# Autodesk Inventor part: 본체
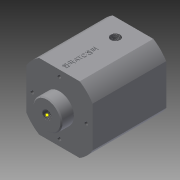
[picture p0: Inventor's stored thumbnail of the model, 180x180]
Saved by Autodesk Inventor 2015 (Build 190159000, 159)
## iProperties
Created: 2020-02
Part Number: 본체
Material: 일반
Document SubType Name: Modeling
Designer: 1026954
Density: 1 g/cm^3
Appearance: 기본값
Author: 1026954
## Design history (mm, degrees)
sketch "스케치1"
  geometry: L1 (-32, -32)-(32, -32); L2 (32, -32)-(32, 32); L3 (32, 32)-(-32, 32); L4 (-32, 32)-(-32, -32); L5 (-32, -32)-(32, 32); L6 (32, -32)-(-32, 32); C1 r 37.5 at (0, 0); 1 further point
  constraints: 12 end point, 2 midpoint, 2 parallel, 1 centre point, 1 coincident, 1 horizontal, 1 perpendicular
  dimensions: "d0" = 75 diameter of C1; "d1" = 64 distance of L3.end L2.end; "d2" = 64 distance of L2.end L1.end
extrude "돌출1" new body sketch "스케치1" distance "d3" = 83; taper "d4" = 0 deg
sketch "스케치2" dims "d5" = 75
  geometry: L1 (-32, 32)-(-19.551, 32); L2 (-32, 32)-(32, 32) reference; L3 (-32, 32)-(-32, 19.551); L4 (-32, -32)-(-32, 32) reference; L5 (32, 32)-(19.551, 32); L6 (32, 32)-(32, 19.551); L7 (32, 32)-(32, -32) reference; L8 (32, -32)-(32, -19.551); L9 (32, -32)-(19.551, -32); L10 (32, -32)-(-32, -32) reference; L11 (-32, -32)-(-32, -19.551); L12 (-32, -32)-(-19.551, -32); 2 further points
  constraints: 16 end point, 8 point on line, 1 coincident, 10 other
extrude "돌출2" cut sketch "스케치2" stored distance "d6" = 82; taper "d7" = 0 deg
sketch "스케치3"
  geometry: L1 (32, -32)-(-32, -32); L2 (-32, -32)-(-32, 32); L3 (-32, 32)-(32, 32); L4 (32, 32)-(32, -32); L5 (32, -32)-(-32, 32); L6 (-32, -32)-(32, 32); C1 r 14 at (0, 0); C2 r 37.5 at (0, 0); 1 further point
  constraints: 12 end point, 2 centre point, 2 coincident, 2 midpoint, 2 parallel, 1 horizontal, 1 perpendicular
  dimensions: "d8" = 28 diameter of C1; "d9" = 75 diameter of C2; "d10" = 64 distance of L2.end L3.end; "d11" = 64 distance of L1.end L2.end
extrude "돌출3" cut sketch "스케치3" distance "d12" = 12; taper "d13" = 0 deg
sketch "스케치4"
  geometry: C1 r 14 at (0, 0) reference; 1 further point
hole "구멍1" sketch "스케치4" at (0, 0) diameter "d14" = 8.917; stored, may be unused: countersink angle "d18" = 90 deg, drill point angle "d20" = 118 deg; dims "d15" = 14, "d16" = 4, "d17" = 2, "d19" = 17
sketch "스케치5"
  geometry: C1 r 4.458 at (0, 0) reference; C2 r 14 at (0, 0) reference; C3 r 2 at (0, 0); 1 further point
  constraints: 1 centre point, 1 coincident
  dimensions: "d21" = 4 diameter of C3
extrude "돌출4" cut sketch "스케치5" stored distance "d22" = 12; taper "d23" = 0 deg
sketch "스케치6"
  geometry: L1 (0, 0)-(0, 26)
  constraints: 2 end point, 1 vertical
  dimensions: "d24" = 26 distance of L1.start L1.end
hole "구멍2" sketch "스케치6" at (0, 26) diameter "d25" = 3.459; stored, may be unused: countersink angle "d29" = 90 deg, drill point angle "d31" = 118 deg; dims "d26" = 10, "d27" = 4, "d28" = 2, "d30" = 12
sketch "스케치7"
  geometry: L1 (39.102, -71)-(0, -71) reference; L2 (0, -71)-(0, 0) reference; L3 (0, 0)-(39.102, 0) reference; L4 (39.102, 0)-(39.102, -71) reference; L5 (19.551, 0)-(19.551, -17); 1 further point
  constraints: 2 end point, 1 midpoint, 1 vertical
  dimensions: "d35" = 17 distance of L5.start L5.end
hole "구멍3" sketch "스케치7" at (19.551, -17) diameter "d36" = 8.917; stored, may be unused: countersink angle "d40" = 90 deg, drill point angle "d42" = 118 deg; dims "d37" = 6, "d38" = 4, "d39" = 2, "d41" = 9
sketch "스케치8"
  geometry: L1 (39.102, -71)-(0, -71) reference; L2 (0, -71)-(0, 0) reference; L3 (0, 0)-(39.102, 0) reference; L4 (39.102, 0)-(39.102, -71) reference; C1 r 4.458 at (19.551, -17) reference; C2 r 2 at (19.551, -17); 1 further point
  constraints: 1 centre point, 1 coincident
  dimensions: "d43" = 4 diameter of C2
extrude "돌출5" cut sketch "스케치8" distance "d44" = 40; taper "d45" = 0 deg
sketch "스케치9"
  geometry: C1 r 20 at (0, 0); 1 further point
  constraints: 1 centre point, 1 coincident
  dimensions: "d46" = 40 diameter of C1
extrude "돌출6" cut sketch "스케치9" distance "d47" = 62; taper "d48" = 0 deg
sketch "스케치10"
  geometry: L1 (0, 0)-(0, -21.224); L2 (0, 0)-(22.517, -13); L3 (0, 0)-(-22.517, -13); L4 (0, 0)-(0, 26); C1 r 1.73 at (0, 26) reference; A1 r 26 centre (0, 0) between (22.517, -13) and (-22.517, -13)
  constraints: 8 end point, 2 point on circle, 2 vertical, 1 centre point, 1 coincident
  dimensions: "d49" = 52 diameter of A1; "d50" = 60 deg angle of L1 L2; "d51" = 60 deg angle of L1 L3
hole "구멍4" sketch "스케치10" at (22.517, -13), (-22.517, -13), (0, 26) diameter "d52" = 3.459; stored, may be unused: countersink angle "d56" = 90 deg, drill point angle "d58" = 118 deg; dims "d53" = 10, "d54" = 4, "d55" = 2, "d57" = 12
sketch "스케치11"
  geometry: L1 (5.551, -71)-(33.551, -71) reference; L2 (5.551, -83)-(33.551, -83) reference; L3 (0, -71)-(39.102, -71) reference; L4 (39.102, -71)-(39.102, 0) reference; L5 (0, 0)-(39.102, 0) reference; L6 (0, 0)-(0, -71) reference; C1 r 4.458 at (19.551, -17) reference; 3 further points
  constraints: 1 midpoint, 1 vertical alignment, 1 other
  dimensions: "d59" = 20 distance from line of L1 point (19.551, -51)
feature "엠보싱1" sketch "스케치11" dims "d0" = 75, "d1" = 64, "d2" = 64, "d60" = 0.5, "d61" = 0
chamfer "모따기2" distance "d65" = 1.8; stored, may be unused: second distance "d66" = 2, angle "d67" = 15 deg
chamfer "모따기3" distance "d68" = 1; stored, may be unused: second distance "d69" = 2, angle "d70" = 45 deg
sketch "스케치12"
  geometry: 1 further point
node "솔리드1"
pattern_circular "원형 패턴1" dims angle "d33" = 360 deg
node "투영된 루프1"
node "투영된 루프2"
node "절단 모서리 투영1"
node "절단 모서리 투영2"
node "절단 모서리 투영3"
node "절단 모서리 투영4"
